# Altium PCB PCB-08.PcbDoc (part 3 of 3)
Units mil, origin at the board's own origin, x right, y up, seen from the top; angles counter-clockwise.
Board outline 2372.23 x 1978.53 mil, 4 copper layers (Top Layer, Plane-1, Plane-2, Bottom Layer), stack 84.834 mil thick; 206 components, 83 nets, 492 pads, 242 vias.
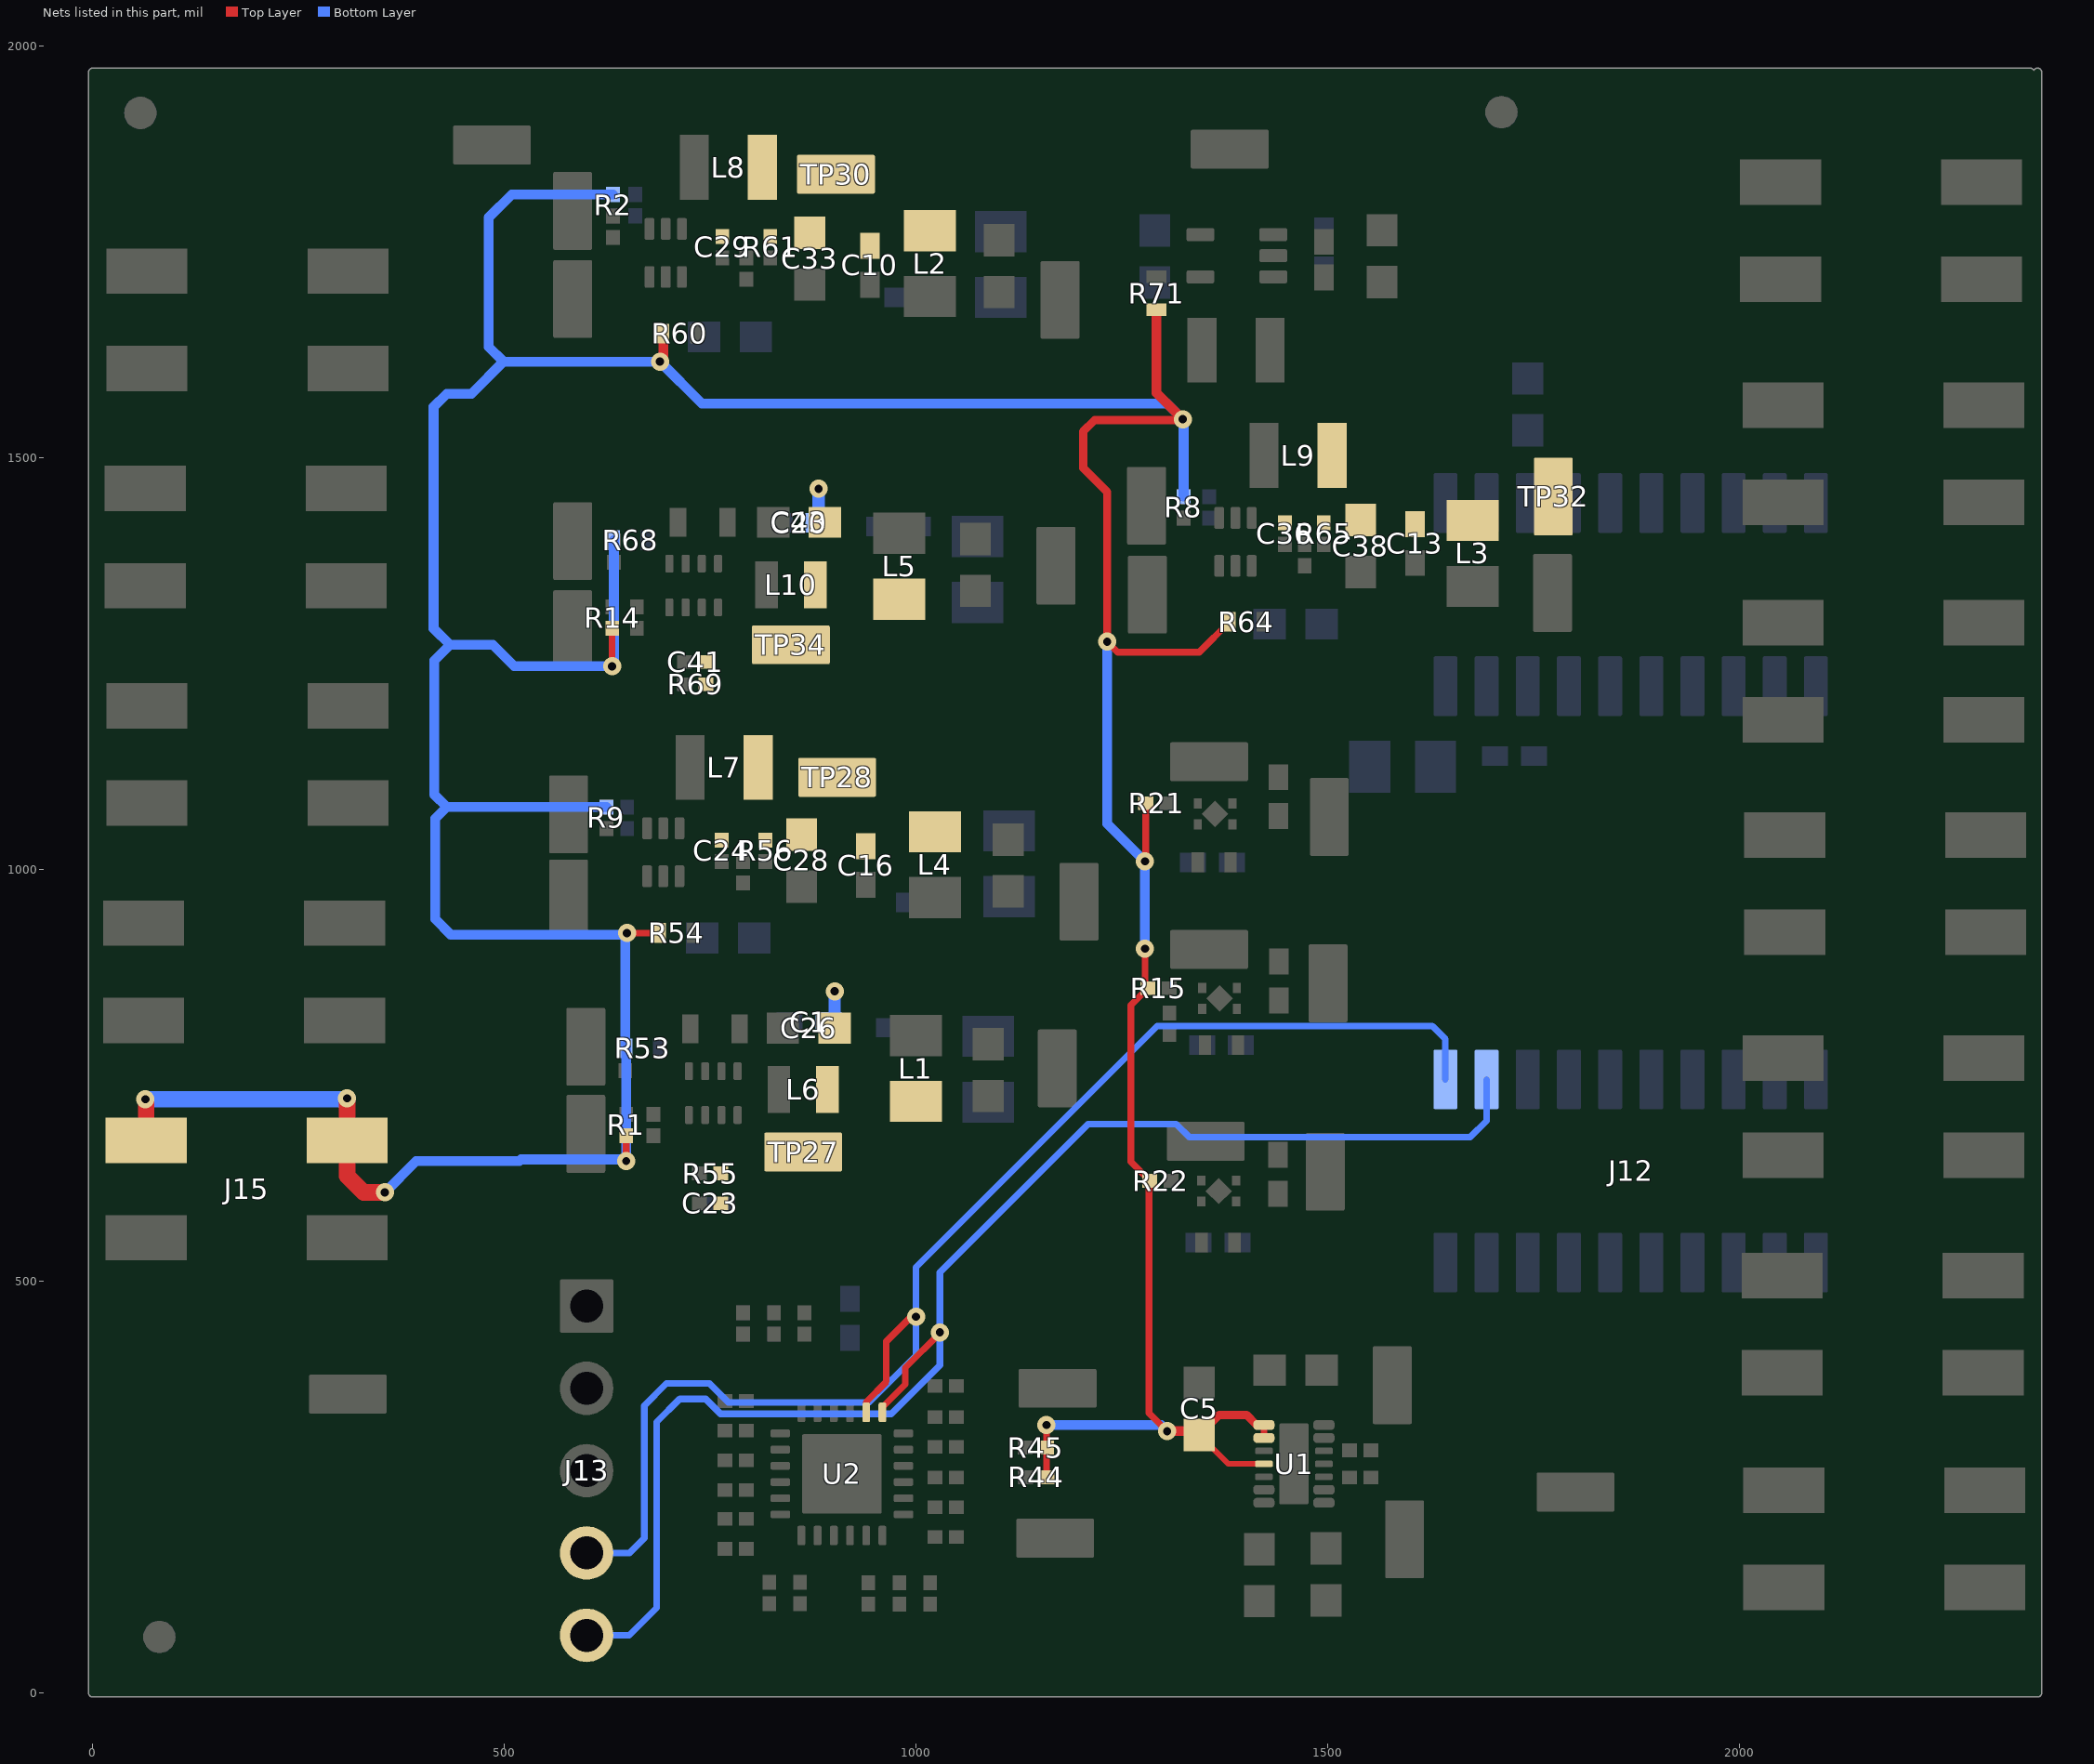
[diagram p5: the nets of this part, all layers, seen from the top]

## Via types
v1: diameter 22, hole 10, Top Layer to Bottom Layer, 231 vias
v2: diameter 19.68, hole 7.87, Top Layer to Bottom Layer, 8 vias
v3: diameter 18, hole 8, Top Layer to Bottom Layer, 3 vias

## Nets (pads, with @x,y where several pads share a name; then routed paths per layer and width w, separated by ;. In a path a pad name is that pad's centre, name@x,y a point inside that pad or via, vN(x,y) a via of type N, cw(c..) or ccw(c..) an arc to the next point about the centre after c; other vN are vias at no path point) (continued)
PLLUP: C5.1 J15.2 R1.1 R2.1 R8.1 R9.1 R14.1 R15.1 R21.1 R22.1 R44.1 R45.1 R53.1 R54.1 R60.1 R64.1 R68.1 R71.1 U1.1 U1.2 U1.4 | length 6272.6
  Top Layer w7: C5.1@1344,313.5 1379.29,278.21 U1.4@1422.58,278.21
  Top Layer w8: v1(631,1247) R14.1@631,1293.01 ; v1(648,646) R1.1@648,677.01 ; v1(649,923) R54.1@689,923 ; v1(1158.49,325.49) R45.1@1158.49,298 1158.49,262.5 R44.1@1158.99,262 ; v1(1232.24,1276.76) 1245,1264 1344,1264 R64.1@1381,1301 ; v1(1278,904) 1278,859.51 R15.1@1281.51,856 1261,835.49 1261,645 R22.1@1284,622 1283,621 1283,340 v1(1305,318) ; v1(1278,1010) 1279.01,1011.01 R21.1@1279.01,1080.5 ; U1.2@1422.58,309.71 U1.1@1422.58,325.46
  Top Layer w10: v1(1232.24,1276.76) 1232.24,1458.76 1203,1488 1203,1532 1217,1546 v1@1325,1546 ; C5.1@1344,313.5 1368.21,337.72 1401.42,337.72 1413.68,325.46 U1.1@1422.58,325.46
  Top Layer w12: v1(689,1617) 693,1621 R60.1@693,1651 ; R71.1@1292,1680 1292,1579 v1(1324,1547) v1@1325,1546 ; v1(1305,318) 1339.5,318 C5.1@1344,313.5
  Top Layer w20: v1(64.05,721.1) 65,720.15 J15.2@65,671 ; v1(309.05,722.22) 309.09,722.17 J15.2@309.09,671 309.09,627.91 329,608 v1(355,608)
  Bottom Layer w12: v1(355,608) 393,646 518.36,646 520.36,648 648,648 R53.1@648,783 647,784 647,921 435,921 416,940 416,1061.98 430.01,1075.99 ; R9.1@624,1075.99 430.01,1075.99 ; R2.1@632,1819.99 508.99,1819.99 481,1792 481,1635 499,1617 ; R68.1@633,1400 633,1249 v1(631,1247) 512,1247 486,1273 434,1273 ; v1(1158.49,325.49) 1297.51,325.49 v1(1305,318) ; v1(1232.24,1276.76) 1232.24,1055.76 v1(1278,1010) v1(1278,904) ; R8.1@1325,1452.99 1325,1546 v1(1324,1547) 1305,1566 740,1566 v1(689,1617) 499,1617 ; 430.01,1075.99 415,1091 415,1254 434,1273 ; 434,1273 414,1293 414,1562 430,1578 460,1578 499,1617
  Bottom Layer w20: v1(64.05,721.1) 307.94,721.1 v1(309.05,722.22)
SCL: J12.4 J13.5 U2.19 | length 1754.7
  Top Layer w8: U2.19@959.21,340.8 959.21,347.21 987,375 987,395 1029,437 v1(1029,438)
  Bottom Layer w8: J13.5@600,70 651.59,70 685,103.41 685,329 713,357 744.53,357 762.53,339 970,339 1029,398 v1(1029,438) 1029,511 1209,691 1316,691 1331.99,675.01 1673.01,675.01 1693,695 J12.4@1693,745.22
SDA: J12.2 J13.4 U2.20 | length 1684.2
  Top Layer w8: U2.20@939.53,340.8 939.53,353.53 964,378 964,427 994,457 v1(1000,457)
  Bottom Layer w8: J13.4@600,170 652,170 670,188 670,349 697,376 749,376 772,353 943,353 1000,410 v1(1000,457) 1000,517 1292.81,809.81 1627.19,809.81 1643,794 J12.2@1643,745.22
V1V1: C20.1 C41.1 C43.1 L5.1 L10.2 R69.1 TP34.1 | length 41.6
  Bottom Layer w15: C20.1@881.62,1421 v1(881.62,1462.62)
V1V2: C16.1 C24.1 C28.1 L4.1 L7.2 R56.1 TP28.1
V1V8: C10.1 C29.1 C33.1 L2.1 L8.2 R61.1 TP30.1
V1V35: C13.1 C36.1 C38.1 L3.1 L9.2 R65.1 TP32.1
V3V3: C1.1 C23.1 C26.1 L1.1 L6.2 R55.1 TP27.1 | length 65.4
  Top Layer w8: TP27.1@838,657 TP27.1@863,657
  Bottom Layer w15: C1.1@893.62,815 901.25,822.63 v1(901.25,852.25)
pads on no net: FID1.1 FID2.1 FID3.1 FID4.1 FID5.1 FID6.1 H1.0 H2.0 H3.0 H4.0 J9.17 J9.18 J9.19 J9.20 J12.13 J12.15 J12.17 J12.18 J12.19 J12.20 LBL1.0 U1.15@1459,252.43 U1.15@1459,304 U2.17 U3.4 U10.4

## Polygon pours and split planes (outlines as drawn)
L2V8 on Top Layer "PWR1-No Net" (solid, pour order 132): 1482,796 1483,797 1551,797 1577,771 1577,700 1577,629 1619,587 2333,587 2346,600 2346,680 2334,693 1691,693 1669,715 1669,806 1564,911 1474,911 1470,907 1470,867 1460,857 1441,857 1441,825 1453,825
1V1 on Top Layer "1V1_L01_P122" (solid, remove dead copper, pour order 122): 956,1496 1159,1496 1209,1446 1209,1322 1195,1308 1146,1308 1129,1325 1129,1358 1108,1379 947,1379 929,1397 929,1485 940,1496
1V8 on Top Layer "1V8_L01_P114" (solid, remove dead copper, pour order 114): 1126,1723 1154,1751 1204,1751 1219,1736 1219,1621 1196,1598 1007,1598 973,1632 973,1715 981,1723
V3V3 on Top Layer "GND-No Net" (solid, pour order 73): 930,867 930,757 937,750 940,747 1029,747 1035,741 1036,740 1036,642 1028,634 1026,632 908,632 902,626 862,586 758,586 758,637 804,637 816,649 816,680 873,680 877,684 879,686 879,759 879,857 879,866 879,871 886,878 920,878 923,878 930,871 930,867
NetL7_1 on Top Layer "GND-No Net" (solid, pour order 77): 710,1037 718,1037 718,1046 743,1071 744,1072 744,1165 712,1165 709,1165 709,1038
V1V2 on Top Layer "GND-No Net" (solid, pour order 81): 757,1027 838,1027 913,1027 925,1015 927,1013 1052,1013 1056,1017 1057,1018 1057,1108 1057,1149 1057,1155 1048,1164 791,1164 791,1081 787,1077 755,1045 754,1045 754,1029 756,1027 758,1027
GND on Top Layer "GND-No Net" (solid, pour order 83): 782,991 782,952 786,948 952,948 954,948 958,952 958,998 842,998 835,991
NetL8_1 on Top Layer "GND-No Net" (solid, pour order 76): 713,1765 721,1765 721,1774 746,1799 747,1800 747,1893 715,1893 712,1893 712,1766
V1V8 on Top Layer "GND-No Net" (solid, pour order 80): 761,1756 842,1756 917,1756 929,1744 931,1742 1043,1742 1049,1748 1049,1884 1040,1893 795,1893 795,1810 791,1806 759,1774 758,1774 758,1758 760,1756 762,1756
GND on Top Layer "GND-No Net" (solid, pour order 82): 786,1724 786,1685 790,1681 956,1681 958,1681 962,1685 962,1731 846,1731 839,1724
GND on Top Layer "GND-No Net" (solid, pour order 90): 1088,1017 1141,1017 1153,1029 1153,1113 1153,1114 1148,1119 1147,1120 1087,1120 1079,1120 1075,1116 1074,1115 1074,1030 1074,1028 1085,1017 1089,1017
V1V1 on Top Layer "GND-No Net" (solid, pour order 75): 737,1259 737,1217 995,1217 1002,1217 1009,1224 1012,1227 1012,1354 949,1354 936,1354 932,1354 911,1375 911,1471 906,1476 870,1476 864,1470 864,1308 854,1298 801,1298 795,1298 789,1292 789,1272 789,1263 785,1259
GND on Top Layer "GND-No Net" (solid, pour order 89): 1078,1745 1131,1745 1143,1757 1143,1841 1143,1842 1138,1847 1137,1848 1077,1848 1069,1848 1065,1844 1064,1843 1064,1758 1064,1756 1075,1745 1079,1745
GND on Top Layer "GND-No Net" (solid, pour order 88): 1098,1358 1045,1358 1033,1346 1033,1262 1033,1261 1038,1256 1039,1255 1099,1255 1107,1255 1111,1259 1112,1260 1112,1345 1112,1347 1101,1358 1097,1358
NetL9_1 on Top Layer "GND-No Net" (solid, pour order 74): 1405,1414 1413,1414 1413,1423 1438,1448 1439,1449 1439,1542 1407,1542 1404,1542 1404,1415
V1V35 on Top Layer "GND-No Net" (solid, pour order 79): 1453,1409 1517,1409 1520,1406 1534,1406 1609,1406 1616,1399 1788,1399 1798,1409 1798,1531 1786,1543 1487,1543 1487,1460 1451,1424 1450,1424 1450,1412
3V3 on Top Layer "GND-No Net" (solid, pour order 92): 968,766 1111,766 1131,766 1138,759 1141,756 1141,717 1141,710 1144,707 1145,706 1193,706 1197,710 1197,847 1190,854 973,854 962,843 962,831 962,778 962,772
1V35 on Top Layer "GND-No Net" (solid, pour order 95): 2341,1371 2347,1377 2347,1479 2340,1486 2336,1487 1864,1487 1829,1487 1820,1478 1820,1390 1812,1382 1646,1382 1635,1371 1635,1279 1643,1271 1784,1271 1797,1284 1798,1284 1798,1308 1809,1319 1955,1319 2007,1371
G5V on Top Layer "GND-No Net" (solid, pour order 97): 1485.05,304.1 1598.1,304.1 1603,309 1603,421 1603,422 1600,425 1476,425 1474,423 1477,420 1477,342 1478,341 1483.55,335.45 1483.55,330.44 1483.55,305.61 1485.05,304.1
3V3 on Top Layer "GND-No Net" (solid, pour order 98): 1435,152 1355,152 1345,142 1345,87 1356,76 1526,76 1536,85 1857,85 1934,162 1935,161 2346,161 2346,30 2325,9 1307,9 1283,33 1283,221 1298,236 1322.96,236 1330,243.04 1330,244 1332,246 1428.22,246 1435.06,238.84 1435,210
G3V3 on Top Layer "GND-No Net" (solid, pour order 99): 1482.92,250.19 1482,249.27 1482,210 1479,207 1479,156 1526,156 1534,148 1542,140 1609,140 1641,140 1649,148 1649,234 1641,242 1573,242 1522,242 1511,253 1486.56,252.95 1482.3,248.68
L1V8B on Top Layer "GND-No Net" (solid, pour order 101): 1526,685 1529,682 1529,531 1541,519 1703,519 1801,421 2346,421 2346,342 2346,339 2346,336 2339,329 1731,329 1600,460 1496,460 1463,493 1463,578 1454,587 1440.23,587 1430.42,596.81 1431,597.39 1431,623 1456,623 1470,637 1470,681 1474,685
L1V8A on Top Layer "GND-No Net" (solid, pour order 106): 1458,1081 1476,1099 1476,1113 1479,1116 1528,1116 1532,1112 1532,1087 1537,1081 1893,1081 2018,956 2348,956 2348,869 2336,857 1956,857 1855,958 1619,958 1581,996 1558,1019 1448,1019 1429,1038 1429,1078 1432,1081
1V2 on Top Layer "GND-No Net" (solid, pour order 107): 2329.36,1248 2348,1229.36 2348,1134 2328,1114 1979,1114 1929,1164 1241,1164 1223,1146 1223,893 1216,886 991,886 979,898 979,990 985,996 1155,996 1167,1008 1167,1229 1186,1248
GND on Top Layer "GND_L01_P148" (solid, remove dead copper, pour order 148): 1522,1387 1567,1387 1570,1390 1617,1390 1619,1390 1622,1387 1622,1346 1622,1277 1614,1269 1611,1266 1543,1266 1459,1266 1450,1275 1449,1276 1449,1356 1449,1369 1458,1378 1459,1379 1479,1379 1514,1379 1522,1387
GND on Bottom Layer "GND_L04_P156" (solid, remove dead copper, pour order 156): 856,321 963,321 963,212 856,212
GND on Bottom Layer "GND_L04_P154" (solid, remove dead copper, pour order 154): 1337.67,1087 1388.67,1087 1388.67,1049 1337.67,1049 1337.67,1087
GND on Bottom Layer "GND_L04_P152" (solid, remove dead copper, pour order 152): 1343,863 1394,863 1394,825 1343,825 1343,863
GND on Bottom Layer "GND_L04_P150" (solid, remove dead copper, pour order 150): 1342,629 1393,629 1393,591 1342,591 1342,629
GND on Bottom Layer "PWR1-No Net" (solid, pour order 142): 1437,330 1436,329 1436,223 1577,223 1602,248 1602,320 1592,330
GND on Bottom Layer "GND-No Net" (solid, pour order 86): 1088,1016.5 1141,1016.5 1153,1028.5 1153,1112.5 1153,1113.5 1148,1118.5 1147,1119.5 1087,1119.5 1079,1119.5 1075,1115.5 1074,1114.5 1074,1029.5 1074,1027.5 1085,1016.5 1089,1016.5
GND on Bottom Layer "GND-No Net" (solid, pour order 84): 1078,1744.5 1131,1744.5 1143,1756.5 1143,1840.5 1143,1841.5 1138,1846.5 1137,1847.5 1077,1847.5 1069,1847.5 1065,1843.5 1064,1842.5 1064,1757.5 1064,1755.5 1075,1744.5 1079,1744.5
GND on Bottom Layer "GND-No Net" (solid, pour order 85): 1098,1358.5 1045,1358.5 1033,1346.5 1033,1262.5 1033,1261.5 1038,1256.5 1039,1255.5 1099,1255.5 1107,1255.5 1111,1259.5 1112,1260.5 1112,1345.5 1112,1347.5 1101,1358.5 1097,1358.5
1V8 on Bottom Layer "1V8_L04_P144" (solid, remove dead copper, pour order 144): 1109,1657 1845,1657 1854,1648 1854,1061 1822,1029 1497,1029 1421,1105 1397,1129 1397,1289 1397,1496 1394,1499 1312,1581 1278,1581 1065,1581 1055,1591 1055,1650 1062,1657
GND on Plane-1 "GND-No Net" (solid, pour order 93): 26,28 2330,28 2330,1935 26,1935
1V8 on Plane-2 "GND-No Net" (solid, remove dead copper, pour order 112): 1207.05,1588.95 1207,1589 1207,1899 1192,1914 900,1914 867,1881 867,1795 844,1772 509,1775 486.05,1797.95 23.05,1797.95 13.05,1787.95 13.05,1695.95 16.05,1692.95 401.05,1692.95 443.05,1650.95 443.05,1595.95 471.05,1567.95 1186.05,1567.95
3V3 on Plane-2 "GND-No Net" (solid, pour order 100): 1418,698.01 1418,903 1415,906 1418,909 1418,984 1388,1014 753,1014 742,1003 742,308 767,283 943,283 957,269 957,208 974,191 1394,191 1418,215
G5V on Plane-2 "GND-No Net" (solid, remove dead copper, pour order 104): 2088.95,1463.05 2198,1354 2198,183 2144,129 2144,37 2126,18 50,18 30,38 30,1002 44,1016 45,1015 678,1015 701,992 701,292 738,255 905,255 934,226 934,194 964,164 1418.68,164 1453,198.32 1453,427 1469,443 1566,443 1589,420 1589,101.03 2004,101.03 2021,118.03 2021,121 2020,122 2019.5,1228.5 1964,1284 1964,1434 1993.05,1463.05
G3V3 on Plane-2 "GND-No Net" (solid, pour order 105): 1978,113 1993,128 1993,166 1992.01,1230.01 1948,1274.02 1948,1356 1942,1362 1807,1362 1710,1265 50,1265 34,1249 34,1224.19 34,1057 47,1044 1428,1044 1455,1017 1459,1017 1459,487 1476,470 1576,470 1612,434 1612,412 1612,141 1640,113
1V1 on Plane-2 "1V1_L03_P118" (solid, remove dead copper, pour order 118): 1709.24,1570 1709.24,1567.76 1725,1552 1725,1278.45 1710,1262.79 1570.21,1262.79 1518,1315 1197,1315 1196,1314 68,1314 28,1354 28,1549 45,1566 47,1567 56,1576 425,1576 454.77,1546.23 1196,1540 1226,1570

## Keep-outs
Keep-Out Layer:
  text ".Layer_Name" at -954,-1863.49 h60

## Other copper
Top Layer:
  text ".Layer_Name" at -954,-1863.49 h60
Plane-1:
  pour cut-out: 1317.07,1584 1455,1584 1455,1679 1316.94,1679
  pour cut-out: 800.02,1315 896,1315 896,1379 799.94,1379
  pour cut-out: 1392.07,1457 1530,1457 1530,1552 1391.94,1552
  pour cut-out: 703.07,1806 841,1806 841,1901 702.94,1901
  pour cut-out: 697.07,1074 835,1074 835,1169 696.94,1169
  pour cut-out: 814.02,699 910,699 910,763 813.94,763
  pour cut-out: 1627.79,1459 1625.32,1456.53 1625.32,1294.11 1719.32,1294.11 1723.32,1298.11 1723.32,1454.11 1715.32,1454.11 1710.32,1459.11 1710.21,1459
  pour cut-out: 975.79,1086 973.32,1083.53 973.32,921.11 1067.32,921.11 1071.32,925.11 1071.32,1081.11 1063.32,1081.11 1058.32,1086.11 1058.21,1086
  pour cut-out: 969.79,1816 967.32,1813.53 967.32,1651.11 1061.32,1651.11 1065.32,1655.11 1065.32,1811.11 1060.31,1816.12
  pour cut-out: 956.87,836.91 948.28,828.33 948.28,665.9 1042.28,665.9 1046.28,669.9 1046.28,825.9 1035.17,837.02
  pour cut-out: 933.47,1450.89 931,1448.42 931,1286 1025,1286 1029,1290 1029,1446 1021,1446 1016,1451 1015.89,1450.89
  text ".Layer_Name" at -915,-1877.49 h60
Plane-2:
  pour cut-out: 933.47,1450.89 931,1448.42 931,1286 1025,1286 1029,1290 1029,1446 1021,1446 1016,1451 1015.89,1450.89
  pour cut-out: 956.87,836.91 948.28,828.33 948.28,665.9 1042.28,665.9 1046.28,669.9 1046.28,825.9 1035.17,837.02
  pour cut-out: 969.79,1816 967.32,1813.53 967.32,1651.11 1061.32,1651.11 1065.32,1655.11 1065.32,1811.11 1060.31,1816.12
  pour cut-out: 975.79,1086 973.32,1083.53 973.32,921.11 1067.32,921.11 1071.32,925.11 1071.32,1068.68 1053.9,1086.1
  pour cut-out: 1627.79,1459 1625.32,1456.53 1625.32,1294.11 1719.32,1294.11 1723.32,1298.11 1723.32,1454.11 1715.32,1454.11 1710.32,1459.11 1710.21,1459
  pour cut-out: 814.02,699 910,699 910,763 813.94,763
  pour cut-out: 697.07,1074 835,1074 835,1169 696.94,1169
  pour cut-out: 703.07,1806 841,1806 841,1901 702.94,1901
  pour cut-out: 1392.07,1457 1530,1457 1530,1552 1391.94,1552
  pour cut-out: 800.02,1315 896,1315 896,1379 799.94,1379
  pour cut-out: 1317.07,1584 1455,1584 1455,1679 1316.94,1679
  text ".Layer_Name" at -975,-1869.49 h60
Bottom Layer:
  text ".Layer_Name" at -954,-1863.49 h60

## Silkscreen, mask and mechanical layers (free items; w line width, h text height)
Top Overlay:
  lines w5: 779,904 779,963.96 785.01,969.97
  text ".Layer_Name" at -954,-1863.49 h60
Bottom Overlay:
  text ".Layer_Name" at -954,-1863.49 h60
Top Paste:
  text ".Layer_Name" at -954,-1863.49 h60
Bottom Paste:
  text ".Layer_Name" at -954,-1863.49 h60
Top Solder:
  text ".Layer_Name" at -954,-1863.49 h60
  text ".Layer_Name" at -954,-1863.49 h60
Bottom Solder:
  rectangle: 1436,223 1485,326
  rectangle: 856,212 963,321
  rectangle: 1341.33,591 1393.33,629
  rectangle: 1342.33,825 1394.33,863
  rectangle: 1337,1049 1389,1087
  text ".Layer_Name" at -954,-1863.49 h60
Drill Guide:
  text ".Layer_Name" at -954,-1863.49 h60
M1 Board Outline:
  lines w10: 2353.2,1968.5 0,1968.5 0,0 2362.2,0 2362.2,1968.5
M2 Board Dimensions:
  rectangle: -1406,-1405 -1031,-1280
  rectangle: -1531,-1280 -1406,-1155
  lines w7: -1531,-1280 -531,-1280 ; -1406,-1405 -1406,-1155 ; -1281,-1405 -1281,-1155 ; -1031,-1405 -1031,-1155 ; -781,-1405 -781,-1155 ; -1531,-1405 -1531,-1155 -531,-1155 -531,-1405 -1531,-1405
M3 3D STEP Top:
  text ".Layer_Name" at -954,-1863.49 h60
M4 3D STEP Bottom:
  text ".Layer_Name" at -954,-1863.49 h60
M5 Assembly Top:
  lines w10: -1823,-1935.17 4777,-1935.17 ; -1823,-1731.83 4779,-1731.83 ; -1823,-1528.5 -1823,-2138.5 2182,-2138.5 4779,-2138.5 4779,-1528.5 -1822.5,-1528.5 -1822.5,-2138.5 -247,-2138.5 ; 642,-2138.5 642,-1528.5 ; 1909,-1731.83 1909,-1528.5 ; 2749,-1731.83 2749,-1528.5 ; 3371,-2145 3371,-1942.17
  text "COMPONENTS MARKED 'DNP' SHOULD NOT BE POPULATED." at -377.5,-1323.5 h60
  text "ASSEMBLY VARIANT:" at -378,-1439 h60
  text ".VariantName" at 658,-1439 h60
  text "PCB VIEWED FROM TOP SIDE" at -1759.5,-1660.67 h60
  text "BOARD #:" at 717,-1660.67 h60
  text ".PRJ_Number" at 1262.5,-1660.67 h60
  text "REV:" at 2107,-1660.67 h60
  text ".PCB_Rev" at 2398.5,-1660.67 h60
  text "SVN REV:" at 2945,-1660.67 h60
  text ".VersionControl_RevNumber" at 3451,-1660.67 h60
  text "'.Layer_Name'" at -929,-1860 h60
  text "TID #:" at 717,-1864 h60
  text ".TID" at 1262.5,-1864 h60
  text "PLOT NAME =" at -1759.5,-2069.34 h60
  text ".plot_File_Name" at -954,-2069.34 h60
  text "GENERATED    :" at 719,-2069.34 h60
  text ".Print_Date" at 1588.5,-2069.34 h60
  text ".Print_Time" at 2317.5,-2069.34 h60
  text "TEXAS INSTRUMENTS" at 3582,-2069.34 h60
M6 Assembly Bottom:
  lines w10: -1823.5,-1732.33 4778.5,-1732.33 ; -1821.5,-1935.67 4778.5,-1935.67 ; -415.5,-2145.5 -415.5,-1942.67 ; 206.5,-1732.33 206.5,-1529 ; 1046.5,-1732.33 1046.5,-1529 ; 2313.5,-2139 2313.5,-1529 ; 3202.5,-2139 4778,-2139 4778,-1529 -1823.5,-1529 -1823.5,-2139 773.5,-2139 4778.5,-2139 4778.5,-1529
  text "COMPONENTS MARKED 'DNP' SHOULD NOT BE POPULATED." at 4571,-1323 h60
  text ".VariantName" at 3527,-1439 h60
  text "ASSEMBLY VARIANT:" at 4566,-1439 h60
  text ".VersionControl_RevNumber" at -495.5,-1661.17 h60
  text "SVN REV:" at 10.5,-1661.17 h60
  text ".PCB_Rev" at 557,-1661.17 h60
  text "REV:" at 848.5,-1661.17 h60
  text ".PRJ_Number" at 1693,-1661.17 h60
  text "BOARD #:" at 2238.5,-1661.17 h60
  text "PCB VIEWED FROM BOTTOM SIDE" at 4715,-1661.17 h60
  text "'.Layer_Name'" at 4297,-1860 h60
  text ".TID" at 1693,-1864.5 h60
  text "TID #:" at 2238.5,-1864.5 h60
  text "TEXAS INSTRUMENTS" at -626.5,-2069.84 h60
  text ".Print_Time" at 638,-2069.84 h60
  text ".Print_Date" at 1367,-2069.84 h60
  text "GENERATED    :" at 2236.5,-2069.84 h60
  text ".plot_File_Name" at 3909.5,-2069.84 h60
  text "PLOT NAME =" at 4715,-2069.84 h60
M9 Title Sheet:
  drawing of 57 lines, arcs and shapes, not listed
  text "1" at -791.16,7031.5 h70
  text "2" at 1704.5,7031.5 h70
  text "3" at 4193.84,7031.5 h70
  text "4" at 6700.51,7031.5 h70
  text "5" at 9199.5,7031.5 h70
  text "6" at 11704.5,7031.5 h70
  text "A" at -1947.5,5888.5 h70
  text "A" at 12852.5,5888.5 h70
  text "B" at -1947.5,3508.5 h70
  text "B" at 12852.5,3508.5 h70
  text "C" at -1947.5,1133.5 h70
  text "C" at 12852.5,1133.5 h70
  text "PROJECT TITLE:" at 9812.5,-727.5 h45
  text ".PRJ_Title" at 9862.5,-860.83 h70
  text "DESIGNED FOR:" at 9812.5,-1028.5 h45
  text ".PRJ_Customer" at 9862.5,-1168.5 h70
  text "D" at -1947.5,-1236.5 h70
  text "D" at 12852.5,-1236.5 h70
  text "FILE NAME:" at 9812.5,-1328.5 h45
  text ".PCB_File_Name_No_Path" at 9862.5,-1448.5 h70
  text "Texas Instruments (TI) and/or its licensors do not warrant the accuracy or completeness of this specification" at 4843,-1610.34 h45
  text "ENGINEER:" at 9812.5,-1618.5 h45
  text "LAYOUT BY:" at 11317.5,-1618.5 h45
  text "or any information contained therein. TI and/or its licensors do not warrant that this design will meet" at 4798.01,-1723 h45
  text ".PRJ_Engineer" at 9862.5,-1773.49 h70
  text ".PCB_Layout" at 11368,-1773.49 h70
  text "the specifications, will be suitable for your application or fit for any particular purpose, or will operate in" at 4798.01,-1835.67 h45
  text "ALTIUM DESIGNER VERSION:" at 11317.5,-1928.5 h45
  text "an implementation. TI and/or its licensors do not warrant that the design is production worthy. You should" at 4798.01,-1948.33 h45
  text "completely validate and test your design implementation to confirm the system functionality for your application." at 4843,-2061 h45
  text ".print_Scale" at 9862.5,-2061.83 h70
  text ".Application_BuildNumber" at 11368,-2061.83 h70
  text "1" at -791.16,-2268.5 h70
  text "2" at 1704.5,-2268.5 h70
  text "3" at 4193.84,-2268.5 h70
  text "4" at 6700.51,-2268.5 h70
  text "5" at 9199.5,-2268.5 h70
  text "6" at 11704.5,-2268.5 h70
M10 Fab Notes:
  drawing of 189 lines, arcs and shapes, not listed
  text "DESIGN INFORMATION" at 10851.02,5351.17 h60
  text "MIN. TRACK WIDTH:" at 10206.46,5219.05 h60
  text "8" at 11302.7,5219.05 h60
  text "MIL" at 11457.46,5219.05 h60
  text "MIN. CLEARANCE:" at 10206.46,5094.92 h60
  text "0.2" at 11242.7,5094.93 h60
  text "mm" at 11457.46,5094.92 h60
  text "MIN. VIA PAD SIZE:" at 10206.46,4970.8 h60
  text "24" at 11272.71,4970.8 h60
  text "MIL" at 11457.46,4970.8 h60
  text "0.05mm (2MIL)" at 10901.46,4840.9 h60
  text "MINIMUM ANNULAR RING" at 9877.23,4832.67 h60
  text "EXTERNAL" at 11609.46,4832.67 h60
  text "PER" at 10077.23,4722.55 h60
  text "IPC-D-275 CLASS 2 LEVEL C" at 10297.23,4722.54 h60
  text "MIL, HOLES" at 11785.46,4622.07 h60
  text "+/-" at 11393,4613.48 h60
  text "+/-" at 12247,4613.48 h60
  text "REGISTRATION TOLERANCES:" at 9877.23,4612.42 h60
  text "METAL" at 11077,4612.42 h60
  text "5" at 11653.2,4612.42 h60
  text "3" at 12486.2,4612.42 h60
  text "MIL" at 12602.46,4612.42 h60
  text "HOLE SIZE TOLERANCE (UNLESS OTHERWISE SPECIFIED):" at 9877.23,4514.1 h60
  text "+/-" at 12247,4511.23 h60
  text "3" at 12486.2,4510.17 h60
  text "MIL" at 12602.46,4510.17 h60
  text "MATERIAL:" at 9802.46,4372.52 h60
  text "FR-4 High Tg" at 10788.9,4244 h60
  text "X" at 10644.46,4236.01 h60
  text "FR-408" at 10223.46,4231.49 h60
  text "OTHER" at 11711.46,4231.49 h60
  text "62 MIL (1.6mm) +/-10%" at 10543.56,4088.46 h60
  text "X" at 10423.46,4086.01 h60
  text "THICKNESS:" at 9877.23,4080.24 h60
  text "OTHER" at 11828.46,4080.24 h60
  text "TOLERANCE:" at 9877.23,3941.92 h60
  text "X" at 10725.46,3941.92 h60
  text "ANSI IPC-6012 TYPE 3 CLASS 2" at 10903.48,3941.92 h60
  text "OTHER +/-" at 10903.46,3797.73 h60
  text "BOW & TWIST:" at 9877.23,3652.54 h60
  text "X" at 10725.46,3652.54 h60
  text "ANSI IPC-6012 TYPE 3 CLASS 2" at 10903.48,3652.54 h60
  text "OTHER +/-" at 10903.46,3505.85 h60
  text "DRILLING:" at 9802.46,3375.23 h60
  text "NC_DRILL FILES" at 11563.46,3270.04 h60
  text "REFERENCE:" at 9877.23,3266.1 h60
  text "X" at 10534.46,3266.01 h60
  text "AS SHOWN" at 10712.46,3266.1 h60
  text "X" at 11435.46,3266.1 h60
  text "OTHER" at 11861.46,3123.85 h60
  text "PTH COPPER THICKNESS:" at 9876.91,3120.32 h60
  text "X" at 11016.14,3120.32 h60
  text "20-30 um" at 11144.14,3120.32 h60
  text "BOARD FINISH:" at 9802.46,2972.73 h60
  text "SILKSCREEN:" at 9957.68,2862.6 h60
  text "X" at 10915.46,2862.6 h60
  text "TOP" at 11032.46,2862.6 h60
  text "X" at 11425.46,2862.6 h60
  text "BOTTOM" at 11543.46,2862.6 h60
  text "SILKSCREEN COLOR:" at 9957.68,2707.41 h60
  text "X" at 10914.46,2707.41 h60
  text "WHITE" at 11032.46,2707.41 h60
  text "OTHER" at 11543.46,2707.41 h60
  text "X" at 11045.46,2563.96 h60
  text "GREEN" at 11163.46,2563.96 h60
  text "OTHER" at 11781.46,2563.96 h60
  text "SOLDER RESIST COLOR:" at 9957.68,2557.1 h60
  text "X" at 11045.46,2409.71 h60
  text "MATTE" at 11163.46,2409.71 h60
  text "SEMI-GLOSS" at 11781,2409.07 h60
  text "IMMERSION GOLD (ENIG)" at 10863.46,2236.94 h60
  text "ENEPIG" at 12201,2229.72 h60
  text "SURFACE FINISH:" at 9802.46,2228.72 h60
  text "X" at 10685.46,2228.72 h60
  text "IMM. TIN/SILVER OR EQUIV" at 10132,2091.4 h60
  text "OTHER" at 11563.46,2087.47 h60
  text "ARRAY/PANEL:" at 9802.46,1932.09 h60
  text "CUT AND TRIM PER M1 BOARD OUTLINE" at 10863.46,1923.87 h60
  text "N.C. ROUTE" at 10863.46,1787.9 h60
  text "X" at 11551.46,1787.9 h60
  text "V. SCORE" at 11729.46,1787.9 h60
  text "CERTIFICATION:" at 9802.46,1658.77 h60
  text "MATERIALS AND WORKMANSHIP FOR ALL PCBS" at 10527.46,1658.77 h60
  text "TO MEET OR EXCEED THE REQUIREMENTS OF:" at 10527.46,1564.71 h60
  text "X" at 10164.97,1436.08 h60
  text "ANSI IPC-A-600F CLASS ->" at 10292.96,1436.08 h60
  text "X" at 11940.97,1436.08 h60
  text "2" at 12050.96,1436.08 h60
  text "1" at 11735.96,1434.58 h60
  text "3" at 12404.96,1434.58 h60
  text "X" at 10976.97,1288.39 h60
  text "RoHS" at 11104.96,1288.39 h60
  text "OTHER" at 11749.36,1288.39 h60
  text "PER ORDER" at 12146.42,1288.39 h60
  text "ALL BOARDS MUST MEET OR EXCEED UL94-V0 REQUIREMENTS." at 9830,1134.57 h60
  text "PCB MUST BEAR THE UL94V-0 UL REGISTERED MATERIAL ID NUMBER" at 9830,1018.5 h60
  text "ADDITIONAL REQUIREMENTS:" at 9802.46,849.08 h60
  text "MICROSECTION:" at 9877.23,741.95 h60
  text "YES" at 10782.96,741.95 h60
  text "REQUIRED" at 11644.46,597.62 h60
  text "BARE BOARD ELEC. TEST:" at 9877.23,594.76 h60
  text "NONE" at 11182.96,594.76 h60
  text "X" at 11526.46,594.76 h60
  text "PER ORDER" at 12236.46,594.76 h60
  text "XX MIL VIAS REQUIRE NON-CONDUCTIVE FILL AND PLANARIZE" at 10045.38,389.82 h59
  text "XX MIL VIAS REQUIRE CONDUCTIVE FILL AND PLANARIZE" at 10053.38,285.84 h60
  text "OUTER XX MIL VIAS REQUIRE 50 OHM SINGLE-ENDED IMPEDANCE" at 10052.39,122.46 h58
  text "LAYER 2 & 3 (INNER LAYERS) XX MIL WIDE, XX MIL SPACE / TRACES REQUIRE 100 OHM DIFFERENTIAL IMPEDANCE" at 10044.39,-113.26 h60
M11 Gerber Information:
  lines w10: -1823,-1935.17 4777,-1935.17 ; -1823,-1731.83 4779,-1731.83 ; -1823,-1528.5 -1823,-2138.5 2182,-2138.5 4779,-2138.5 4779,-1528.5 -1822.5,-1528.5 -1822.5,-2138.5 -247,-2138.5 ; 642,-2138.5 642,-1528.5 ; 1909,-1731.83 1909,-1528.5 ; 2749,-1731.83 2749,-1528.5 ; 3371,-2145 3371,-1942.17
  text "ALL ARTWORK VIEWED FROM TOP SIDE" at -1759.5,-1660.67 h60
  text "BOARD #:" at 717,-1660.67 h60
  text ".PRJ_Number" at 1262.5,-1660.67 h60
  text "REV:" at 2107,-1660.67 h60
  text ".PCB_Rev" at 2398.5,-1660.67 h60
  text "SVN REV:" at 2945,-1660.67 h60
  text ".VersionControl_RevNumber" at 3451,-1660.67 h60
  text "LAYER NAME =" at -1759.5,-1863.49 h60
  text "TID #:" at 717,-1864 h60
  text ".TID" at 1262.5,-1864 h60
  text "PLOT NAME =" at -1759.5,-2069.34 h60
  text ".plot_File_Name" at -954,-2069.34 h60
  text "GENERATED    :" at 719,-2069.34 h60
  text ".Print_Date" at 1588.5,-2069.34 h60
  text ".Print_Time" at 2317.5,-2069.34 h60
  text "TEXAS INSTRUMENTS" at 3582,-2069.34 h60
M12 Stackup:
  drawing of 295 lines, arcs and shapes, not listed
  text "Layer" at 8266.84,6825 h60
  text "Name" at 8676.76,6825 h60
  text "Material" at 9606.5,6825 h60
  text "Thickness" at 10466.27,6825 h60
  text "Constant" at 11116.1,6825 h60
  text "Board Layer Stack" at 11685.96,6825 h60
  text "1" at 8266.84,6705 h60
  text "Top Overlay" at 8676.76,6705 h60
  text "2" at 8266.84,6585 h60
  text "Top Solder" at 8676.76,6585 h60
  text "Solder Resist" at 9606.5,6585 h60
  text "0.40mil" at 10466.27,6585 h60
  text "3.5" at 11116.1,6585 h60
  text "3" at 8266.84,6465 h60
  text "Top Layer" at 8676.76,6465 h60
  text "Copper" at 9606.5,6465 h60
  text "1.40mil" at 10466.27,6465 h60
  text "4" at 8266.84,6345 h60
  text "Dielectric1" at 8676.76,6345 h60
  text "FR-4" at 9606.5,6345 h60
  text "59.20mil" at 10466.27,6345 h60
  text "4.8" at 11116.1,6345 h60
  text "5" at 8266.84,6225 h60
  text "Plane-1" at 8676.76,6225 h60
  text "Copper" at 9606.5,6225 h60
  text "1.42mil" at 10466.27,6225 h60
  text "6" at 8266.84,6105 h60
  text "Dielectric 2" at 8676.76,6105 h60
  text "10.00mil" at 10466.27,6105 h60
  text "4.2" at 11116.1,6105 h60
  text "7" at 8266.84,5985 h60
  text "Plane-2" at 8676.76,5985 h60
  text "Copper" at 9606.5,5985 h60
  text "1.42mil" at 10466.27,5985 h60
  text "8" at 8266.84,5865 h60
  text "Dielectric 3" at 8676.76,5865 h60
  text "10.00mil" at 10466.27,5865 h60
  text "4.2" at 11116.1,5865 h60
  text "9" at 8266.84,5745 h60
  text "Bottom Layer" at 8676.76,5745 h60
  text "Copper" at 9606.5,5745 h60
  text "1.40mil" at 10466.27,5745 h60
  text "10" at 8266.84,5625 h60
  text "Bottom Solder" at 8676.76,5625 h60
  text "Solder Resist" at 9606.5,5625 h60
  text "0.40mil" at 10466.27,5625 h60
  text "3.5" at 11116.1,5625 h60
  text "11" at 8266.84,5505 h60
  text "Bottom Overlay" at 8676.76,5505 h60
M13 Component Bodies Top:
  text ".Layer_Name" at -954,-1863.49 h60
M14 Component Bodies Bottom:
  text ".Layer_Name" at -954,-1863.49 h60
M15 Courtyards Top:
  text ".Layer_Name" at -954,-1863.49 h60
M16 Courtyards Bottom:
  text ".Layer_Name" at -954,-1863.49 h60
Drill Drawing:
  circle w10: c4653.62,3670.83 r33.33
  lines w10: 4620.29,3487.5 4686.96,3487.5 4686.96,3554.17 4620.29,3554.17 4620.29,3487.5 ; 4620.29,3820.83 4653.62,3787.5 4686.96,3820.83 4653.62,3854.17 4620.29,3820.83 ; 4620.29,3954.17 4636.96,3954.17 4636.96,3937.5 4670.29,3937.5 4670.29,3954.17 4686.96,3954.17 4686.96,3987.5 4670.29,3987.5 4670.29,4004.17 4636.96,4004.17 4636.96,3987.5 4620.29,3987.5 4620.29,3954.17
  lines w15: 4560.5,3442.5 9585.13,3442.5 ; 4560.5,4042.5 9585.13,4042.5 ; 5111.38,3292.5 5111.38,4192.5 ; 5711.22,3292.5 5711.22,4192.5 ; 6800.9,3292.5 6800.9,4192.5 ; 7306.78,3292.5 7306.78,4192.5 ; 8040.58,3292.5 8040.58,4192.5 ; 4560.5,3292.5 9585.13,3292.5 9585.13,4192.5 4560.5,4192.5 4560.5,3292.5
  text "Drill Table" at 4651,4288 h60
  text "Symbol" at 4650.5,4087.5 h72
  text "Count" at 5156.38,4087.5 h72
  text "Hole Size" at 5756.22,4087.5 h72
  text "Plated" at 6845.9,4087.5 h72
  text "Hole Type" at 7351.78,4087.5 h72
  text "Drill Layer Pair" at 8085.58,4087.5 h72
  text "8" at 5156.38,3937.5 h60
  text "7.87mil (0.200mm)" at 5756.22,3937.5 h60
  text "PTH" at 6845.9,3937.5 h60
  text "Round" at 7351.78,3937.5 h60
  text "Top Layer - Bottom Layer" at 8085.58,3937.5 h60
  text "3" at 5156.38,3787.5 h60
  text "8.00mil (0.203mm)" at 5756.22,3787.5 h60
  text "PTH" at 6845.9,3787.5 h60
  text "Round" at 7351.78,3787.5 h60
  text "Top Layer - Bottom Layer" at 8085.58,3787.5 h60
  text "231" at 5156.38,3637.5 h60
  text "10.00mil (0.254mm)" at 5756.22,3637.5 h60
  text "PTH" at 6845.9,3637.5 h60
  text "Round" at 7351.78,3637.5 h60
  text "Top Layer - Bottom Layer" at 8085.58,3637.5 h60
  text "5" at 5156.38,3487.5 h60
  text "40.00mil (1.016mm)" at 5756.22,3487.5 h60
  text "PTH" at 6845.9,3487.5 h60
  text "Round" at 7351.78,3487.5 h60
  text "Top Layer - Bottom Layer" at 8085.58,3487.5 h60
  text "247 Total" at 5156.38,3337.5 h60
  text "Drill Tolerance" at 5587,2771 h60
  text "For PTH +/- 3 mils. / For 7.874 mil drill: apply 0/-7.874 mil." at 5584,2455 h60
  text "For 10 mil drill: +/- 10 Mil." at 5584,2321 h60
  text "'.Layer_Name'" at -943,-1878 h60
M17 Embedded Cavity:
  text ".Layer_Name" at -954,-1863.49 h60
M18 Embedded Assembly:
  text ".Layer_Name" at -954,-1863.49 h60
M19 Embedded Keepout:
  text ".Layer_Name" at -954,-1863.49 h60

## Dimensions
0,0 to 0,1968.5 on M2 Board Dimensions
0,0 to 2362.2,0 on M2 Board Dimensions
-1531,-1405 to -531,-1405 on M2 Board Dimensions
